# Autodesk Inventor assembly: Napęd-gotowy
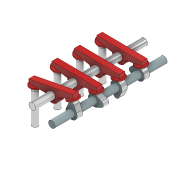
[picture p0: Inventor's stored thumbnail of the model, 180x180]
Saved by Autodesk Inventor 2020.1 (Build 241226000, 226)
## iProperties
Manager: www.cadconsulting.pl
Company: Fabian Stasiak CAD Consulting
Created: 2005-10
Part Number: Napęd-gotowy
Document SubType Name: Assembly
Designer: F.Stasiak
Author: F.Stasiak
Subject: Zbiór ćwiczeń. Autodesk Inventor 2020. Kurs podstawowy
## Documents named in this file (6)
- C:\2020_Kurs_podstawowy\R6 Zespoły\Wiązania\Napęd\Napęd-gotowy.iam
- C:\2020_Kurs_podstawowy\R6 Zespoły\Wiązania\Napęd\Popychacz.ipt
- C:\2020_Kurs_podstawowy\R6 Zespoły\Wiązania\Napęd\Wałek.ipt
- C:\2020_Kurs_podstawowy\R6 Zespoły\Wiązania\Napęd\Szablon.ipt
- C:\2020_Kurs_podstawowy\R6 Zespoły\Wiązania\Napęd\Wałek z krzywkami.ipt
- C:\2020_Kurs_podstawowy\R6 Zespoły\Wiązania\Napęd\Trzpień.ipt
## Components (11 placed, 5 different names)
1. Szablon:1 — Równoległy:2, Zestawiający:1, Zestawiający:4, Zestawiający:15, Zestawiający:17, Zestawiający:19, Zestawiający:21
2. Wałek:1 — Zestawiający:1, Zestawiający:2, Zestawiający:7, Zestawiający:8, Zestawiający:9, Zestawiający:10
3. Wałek z krzywkami:1 — Równoległy:3, Zestawiający:4, Zestawiający:5, NAPĘD, Przejściowy:1, Równoległy:4, Równoległy:5, Równoległy:6, Przejściowy:2, Przejściowy:3, Przejściowy:4
4. Popychacz:1 — Zestawiający:5, Zestawiający:7, Przejściowy:1, Styczny:1, Zestawiający:22
5. Popychacz:2 — Zestawiający:8, Równoległy:4, Przejściowy:2, Zestawiający:16, Styczny:2
6. Popychacz:3 — Zestawiający:9, Równoległy:5, Przejściowy:3, Zestawiający:18, Styczny:3
7. Popychacz:4 — Zestawiający:10, Równoległy:6, Przejściowy:4, Zestawiający:20, Styczny:4
8. Trzpień:1 — Styczny:1, Zestawiający:21, Zestawiający:22
9. Trzpień:2 — Zestawiający:15, Zestawiający:16, Styczny:2
10. Trzpień:3 — Zestawiający:17, Zestawiający:18, Styczny:3
11. Trzpień:4 — Zestawiający:19, Zestawiający:20, Styczny:4
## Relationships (30: Mate 16, Flush 5, Transitional 4, Tangent 4, Angle 1)
- Równoległy:2 [Flush]: Szablon:1
- Zestawiający:1 [Mate]: Szablon:1 ↔ Wałek:1
- Zestawiający:2 [Mate]: Wałek:1
- Równoległy:3 [Flush]: Wałek z krzywkami:1
- Zestawiający:4 [Mate]: Szablon:1 ↔ Wałek z krzywkami:1
- Zestawiający:5 [Mate]: Wałek z krzywkami:1 ↔ Popychacz:1
- Zestawiający:7 [Mate]: Wałek:1 ↔ Popychacz:1
- Przejściowy:1 [Transitional]: Wałek z krzywkami:1 ↔ Popychacz:1
- Zestawiający:8 [Mate]: Wałek:1 ↔ Popychacz:2
- Zestawiający:9 [Mate]: Wałek:1 ↔ Popychacz:3
- Zestawiający:10 [Mate]: Wałek:1 ↔ Popychacz:4
- Równoległy:4 [Flush]: Wałek z krzywkami:1 ↔ Popychacz:2
- Równoległy:5 [Flush]: Wałek z krzywkami:1 ↔ Popychacz:3
- Równoległy:6 [Flush]: Wałek z krzywkami:1 ↔ Popychacz:4
- Przejściowy:2 [Transitional]: Wałek z krzywkami:1 ↔ Popychacz:2
- Przejściowy:3 [Transitional]: Wałek z krzywkami:1 ↔ Popychacz:3
- Przejściowy:4 [Transitional]: Wałek z krzywkami:1 ↔ Popychacz:4
- Styczny:1 [Tangent]: Popychacz:1 ↔ Trzpień:1
- Zestawiający:15 [Mate]: Szablon:1 ↔ Trzpień:2
- Zestawiający:16 [Mate]: Popychacz:2 ↔ Trzpień:2
- Styczny:2 [Tangent]: Popychacz:2 ↔ Trzpień:2
- Zestawiający:17 [Mate]: Szablon:1 ↔ Trzpień:3
- Zestawiający:18 [Mate]: Popychacz:3 ↔ Trzpień:3
- Styczny:3 [Tangent]: Popychacz:3 ↔ Trzpień:3
- Zestawiający:19 [Mate]: Szablon:1 ↔ Trzpień:4
- Zestawiający:20 [Mate]: Popychacz:4 ↔ Trzpień:4
- Styczny:4 [Tangent]: Popychacz:4 ↔ Trzpień:4
- Zestawiający:21 [Mate]: Szablon:1 ↔ Trzpień:1
- Zestawiający:22 [Mate]: Popychacz:1 ↔ Trzpień:1
- NAPĘD [Angle]: Wałek z krzywkami:1
